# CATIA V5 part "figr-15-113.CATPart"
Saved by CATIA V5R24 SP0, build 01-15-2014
Part number: Part1
Bounding box of the stored display mesh (mm): x -55.37 to 68.649, y -21.457 to 35.984, z 0 to 57.441
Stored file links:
  D:\KAVITA\CATIA V5-6R2014 Project_ Kavita\CATIA V5-6R2014_partfiles\Partfiles\c15_catia_v5-6r2014_prt\figr-15-113.CATPart
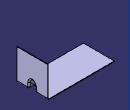
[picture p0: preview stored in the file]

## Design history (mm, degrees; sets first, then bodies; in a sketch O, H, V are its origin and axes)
SheetMetalParameters1: Thickness 1, BendRadius 2, KFactor 0.400515 {= log(min(100,max(20*SheetMetalParameters1.BendRadius,SheetMetalParameters1.Thickness)/SheetMetalParameters1.Thickness))/log(100)/2}, ReliefRadialLength 1, ReliefAxialLength 2, MinimumBendRadius 0
Body1 (main body)
  Sketch1 on xy-plane, origin (0, 0, 0), H (1, 0, 0), V (0, 1, 0)
    line L1 (-55.3695, 35.9836) -> (67.649, 35.9836)
    line L2 (67.649, 35.9836) -> (67.649, -21.4575)
    line L3 (67.649, -21.4575) -> (-55.3695, -21.4575)
    line L4 (-55.3695, -21.4575) -> (-55.3695, 35.9836)
    horizontal: L1 H, L3 H
    vertical: L2 V, L4 V
  Wall1: Thickness 1, Profile Sketch1
  d_NewWallOnEdge1: NewWallOnEdge_Edge edge [face of Wall1 | face of Wall1], NewWallOnEdge_Length 57.4411, NewWallOnEdge_HeightLimitOffset 0, NewWallOnEdge_WidthOffset1 0, NewWallOnEdge_WidthOffset2 0, NewWallOnEdge_Angle 90, NewWallOnEdge_BendRadiusValue 2 {= SheetMetalParameters1.BendRadius}, NewWallOnEdge_BendTable SheetMetalParameters1, KFacteur 0.400515 {= log(min(100,max(20*d_NewWallOnEdge1.Radius,SheetMetalParameters1.Thickness)/SheetMetalParameters1.Thickness))/log(100)/2}
  Sketch2 on , origin (67.7759, 6.9809, 0.8843), H (0.7052, 0, 0.709), V (0, -1, 0)
    point P1 (0, 0)
  d_Stamp1: Stamp_FilletRadius 2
